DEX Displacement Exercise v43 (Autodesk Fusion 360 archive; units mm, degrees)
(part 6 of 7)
sketch "Sketch35" plane through (0, 0, 0) normal (0, 0, 1) x axis (1, 0, 0)
  line L1 (8, 6) -> (-6, 6)
  line L2 (8, -10) -> (8, 6)
  line L3 (-6, -10) -> (8, -10)
  line L4 (-6, 6) -> (-6, -10)
  line L5 (5.46, 30) -> (5.46, 6)
  line L6 (8, 21) -> (8, 6)
  line L7 (10, 21) -> (8, 21)
  line L8 (10, -10) -> (10, 21)
  line L9 (20, -10) -> (10, -10)
  line L10 (20, 30) -> (20, -10)
  line L11 (5.46, 30) -> (20, 30)
  line L12 (5.46, 21) -> (8, 21)
  circle C1 centre (0, 0) radius 8
  circle C2 centre (0, 0) radius 3
  circle C3 centre (0, 0) radius 4.5
  circle C4 centre (6, -6) radius 2.5
  circle C5 centre (15, 0) radius 2.7
  circle C6 centre (15, 25) radius 2.7
  circle C7 centre (15, 25) radius 1.625
  circle C8 centre (15, 0) radius 1.625
  circle C9 centre (15, 15) radius 2.7
  circle C10 centre (15, 15) radius 1.625
  circle C11 centre (15, -6) radius 2
  circle C12 centre (15, -6) radius 1.9
  circle C13 centre (15, 15) radius 3.625
  circle C14 centre (15, 25) radius 3.625
  circle C15 centre (15, 0) radius 3.625
  point P9 (4.5, 0)
  point P2 (0, 0)
  point P4 (0, 0)
  point P3 (0, 0)
  point P1 (0, 0)
  point P11 (5.46, 6)
  point P12 (5.46, 30)
  point P18 (5.46, 30)
  point P7 (8, -10)
  point P19 (15, 0)
  point P20 (15, 25)
  point P23 (5.46, 21)
  point P26 (15, -6)
  point P21 (15, 25)
  point P25 (15, 15)
  point P29 (11.375, 15)
  point P10 (6, -6)
  point P13 (8, 21)
  point P14 (10, 21)
  point P6 (8, 6)
  point P15 (10, -10)
  point P16 (20, -10)
  point P24 (15, 15)
  horizontal L1
  vertical L2
  horizontal L3
  vertical L4
  coincident C3 P9
  horizontal P2 P9
  coincident P2 P4
  coincident P2 P3
  coincident P1 P4
  coincident L1 P11
  perpendicular L1 L5
  perpendicular L1 L6
  perpendicular L6 L7
  perpendicular L7 L8
  perpendicular L8 L9
  perpendicular L9 L10
  perpendicular L10 L11
  coincident P12 P18
  coincident P7 L9
  horizontal P1 P19
  equal C5 C6
  vertical P19 P20
  concentric C6 C7
  concentric C5 C8
  equal C7 C8
  coincident L5 P23
  perpendicular L5 L12
  equal C6 C9
  concentric C9 C10
  vertical P19 P26
  concentric C11 C12
  vertical P21 P25
  concentric C10 C13
  coincident C13 P29
  horizontal P25 P29
  concentric C7 C14
  concentric C5 C15
  equal C14 C15
  equal C13 C14
  dimension "d1328" diameter C1 = 16 (= "od_bearings")
  dimension "d1329" diameter C2 = 6 (= "hw_m4insert_d")
  dimension "d1330" diameter C3 = 9
  dimension "d1361" distance P2 L1 = 6
  dimension "d1362" distance P2 L3 = 10
  dimension "d1363" distance P4 L4 = 6 (= "d1361")
  dimension "d1458" diameter C4 = 5
  dimension "d1459" distance L2 P10 = 2
  dimension "d1460" distance P2 P10 = 6
  dimension "d1461" distance L5 L6 = 2.54
  dimension "d1462" distance P13 P14 = 2
  dimension "d1463" distance P6 P13 = 15
  dimension "d1464" distance P4 P7 = 8
  dimension "d1465" distance P15 P16 = 10
  dimension "d1467" distance P13 L11 = 9
  dimension "d1468" distance L11 P20 = 5
  dimension "d1469" diameter C6 = 5.4 (= "hw_m3insert_d")
  dimension "d1470" distance L10 P19 = 5 (= "d1465 / 2")
  dimension "d1471" diameter C7 = 3.25
  dimension "d1502" = 26
  dimension "d1503" = 41
  dimension "d1506" distance P20 P24 = 10
  dimension "d1507" diameter C10 = 3.25
  dimension "d1508" distance L9 P26 = 4
  dimension "d1509" diameter C11 = 4
  dimension "d1510" distance C11 C12 = 0.1
  dimension "d1528" diameter C13 = 7.25
  dimension "d1529" = 1.25
  dimension "d1447" leftDistance = 0.5
  dimension "d1449" distance = 5
  dimension "d1450" distance = 15
  dimension "d1452" distance = 5
  dimension "d1453" distance = 4.9
  dimension "d1454" distance = 4.9
  dimension "d1455" distance = 5
  dimension "d1456" distance = 24.9
  dimension "d531" countU = 13 (= "nh_gantry_length + 1")
  dimension "d532" CountV = 9 (= "nh_gantry_width + 1")
  dimension "d533" uSpaceDistance = 10
  dimension "d534" vSpaceDistance = -10
  dimension "d535" diameter = 3.3 (= "hw_m4_tappedwj")
  dimension "d541" uSpaceDistance = 10
  dimension "d542" vSpaceDistance = 10
  dimension "d560" distance = 6.6 (= "t_sheet_MAIN")
  dimension "d563" distance = 5 (= "t_bearings")
  dimension "d564" distance = 16 (= "od_bearings")
  dimension "d565" angle = 45 (= "d566")
  dimension "d566" angle = 45
  dimension "d567" distance = 10 (= "l_shoulder_thread")
  dimension "d568" distance = 6.6 (= "t_sheet_MAIN")
  dimension "d569" distance = 45 (= "( ( nh_gantry_width * 10 ) * 1 mm + 10 mm ) / 2")
  dimension "d571" distance = 4.5 (= "hw_shoulder_headHeight + 0.5 mm")
  dimension "d572" distance = 4.5 (= "hw_shoulder_headDiameter / 2")
  dimension "d574" distance = 8.8037
  dimension "d576" distance = 0.5
  dimension "d577" distance = 0.5
  dimension "d580" distance = 0.5
  dimension "d581" distance = 3.5 (= "hw_m4insert_d / 2 + 0.5 mm")
  dimension "d582" distance = 3.5 (= "d581")
  dimension "d583" distance = 2.1
  dimension "d584" distance = 0.8383
  dimension "d586" distance = 1.269 (= "0.5 mm + 0.769 mm")
  dimension "d587" distance = 5
  dimension "d588" distance = 10
  dimension "d589" distance = 5
  dimension "d590" AlongDistance = 65 (= "( nh_gantry_length * 10 + 10 ) / 2 * 1 mm")
  dimension "d591" TaperAngle = 0
  dimension "d597" ProfileOffset = 0.25 (= "carriage_offsets")
  dimension "d599" TaperAngle = 0
  dimension "d601" diameter = 16 (= "od_bearings")
  dimension "d602" diameter = 6 (= "hw_m4insert_d")
  dimension "d603" diameter = 4
  dimension "d604" distance = 0.25
  dimension "d606" AlongDistance = -20
  dimension "d607" TaperAngle = 0
  dimension "d608" ProfileOffset = 0.5
  dimension "d609" AlongDistance = 5 (= "t_bearings")
  dimension "d610" TaperAngle = 0
  dimension "d612" distance = 0.25
  dimension "d613" diameter = 4
  dimension "d614" diameter = 6 (= "hw_m4insert_d")
  dimension "d615" diameter = 16 (= "od_bearings")
  dimension "d616" AlongDistance = -20
  dimension "d617" TaperAngle = 0
  dimension "d618" ProfileOffset = 0.5
  dimension "d619" AlongDistance = 5 (= "t_bearings")
  dimension "d620" TaperAngle = 0
  dimension "d621" AlongDistance = 670 (= "l_actual_complete")
  dimension "d622" TaperAngle = 0
  dimension "d623" distance = 0.1
  dimension "d624" distance = 1.6455
  dimension "d625" distance = 3.4128
  dimension "d626" distance = 13.2 (= "0.5 in + 0.5 mm")
  dimension "d628" distance = 5
  dimension "d630" distance = 30
  dimension "d631" diameter = 4.064 (= "hw_n6_thru")
  dimension "d636" diameter = 6.6548 (= "hw_n6_flathead")
  dimension "d637" diameter = 3.1 (= "hw_n6_thread")
  dimension "d638" distance = 4
  dimension "d639" distance = 4 (= "d638")
  dimension "d641" TaperAngle = 0
  dimension "d642" ProfileOffset = 0
  dimension "d643" Side1Offset = 0
  dimension "d644" TaperAngle = 0
  dimension "d645" ProfileOffset = 0
  dimension "d646" Side1Offset = 0
  dimension "d647" TaperAngle = 0
  dimension "d648" distance = 5
  dimension "d649" distance = 0.75
  dimension "d650" ProfileOffset = 0
  dimension "d651" Side1Offset = 0
  dimension "d652" TaperAngle = 0
  dimension "d653" AlongDistance = 21
  dimension "d654" TaperAngle = 0
  dimension "d655" distance = 1
  dimension "d656" ProfileOffset = 0
  dimension "d657" Side1Offset = 0
  dimension "d658" TaperAngle = 0
  dimension "d659" AlongDistance = 12
  dimension "d660" TaperAngle = 0
  dimension "d661" Side1Offset = 0
  dimension "d662" TaperAngle = 0
  dimension "d667" Radius = 4
  dimension "d669" Radius = 4
  dimension "d670" Radius = 1
  dimension "d673" Radius = 0.5
  dimension "d674" Radius = 0.5
  dimension "d675" Radius = 0.5
  dimension "d676" Radius = 0.5
  dimension "d677" Radius = 0.2
  dimension "d680" distance = 40
  dimension "d681" distance = 6
  dimension "d691" distance = 2.54
  dimension "d692" distance = 0.5 (= "d689")
  dimension "d693" distance = 0.5
  dimension "d696" distance = 0.5
  dimension "d697" distance = 5
  dimension "d701" distance = 1.7
  dimension "d702" distance = 1.7 (= "d701")
  dimension "d706" distance = 2.54 (= "d691")
  dimension "d707" distance = 3.5
  dimension "d708" distance = 0.5
  dimension "d709" ProfileOffset = 0
  dimension "d710" Side1Offset = 0
  dimension "d711" TaperAngle = 0
  dimension "d712" ProfileOffset = 0
  dimension "d713" Side1Offset = 5
  dimension "d714" TaperAngle = 0
  dimension "d715" Side1Offset = 0
  dimension "d716" TaperAngle = 0
  dimension "d717" distance = 0.75
  dimension "d718" distance = 1.7
  dimension "d719" diameter = 16 (= "od_bearings")
  dimension "d720" diameter = 6 (= "hw_m4insert_d")
  dimension "d721" diameter = 4
  dimension "d722" distance = 0.25
  dimension "d723" AlongDistance = -19
  dimension "d724" TaperAngle = 0
  dimension "d725" distance = 1
  dimension "d726" ProfileOffset = 0.5
  dimension "d727" AlongDistance = 5 (= "t_bearings")
  dimension "d728" TaperAngle = 0
  dimension "d729" diameter = 4
  dimension "d730" diameter = 6 (= "hw_m4insert_d")
  dimension "d731" diameter = 16 (= "od_bearings")
  dimension "d732" distance = 1
  dimension "d733" distance = 0.25
  dimension "d734" AlongDistance = -26
  dimension "d735" TaperAngle = 0
  dimension "d736" ProfileOffset = 0.5
  dimension "d737" AlongDistance = 5 (= "t_bearings")
  dimension "d738" TaperAngle = 0
  dimension "d739" distance = 6
  dimension "d740" ProfileOffset = 0
  dimension "d741" Side1Offset = 0
  dimension "d742" TaperAngle = 0
  dimension "d743" Radius = 4
  dimension "d744" distance = -1
  dimension "d745" AlongDistance = 32
  dimension "d746" TaperAngle = 0
  dimension "d747" distance = 0.5
  dimension "d748" distance = 1
  dimension "d749" ProfileOffset = 0
  dimension "d750" AlongDistance = 3
  dimension "d751" TaperAngle = 0
  dimension "d752" ProfileOffset = 0
  dimension "d753" Side1Offset = 0
  dimension "d754" TaperAngle = 0
  dimension "d755" Side1Offset = 0
  dimension "d756" TaperAngle = 0
  dimension "d757" ProfileOffset = 0
  dimension "d758" Side1Offset = 0
  dimension "d759" TaperAngle = 0
  dimension "d760" AlongDistance = 12
  dimension "d761" TaperAngle = 0
  dimension "d762" AlongDistance = -37
  dimension "d763" TaperAngle = 0
  dimension "d764" Side1Offset = 0.5
  dimension "d765" TaperAngle = 0
  dimension "d767" Radius = 3
  dimension "d768" Radius = 2
  dimension "d770" Radius = 3
  dimension "d771" Radius = 3
  dimension "d772" distance = 3
  dimension "d773" distance = 3
  dimension "d774" Radius = 1
  dimension "d775" Radius = 0.5
  dimension "d776" Radius = 2
  dimension "d777" diameter = 5.4 (= "hw_m3insert_d")
  dimension "d778" diameter = 3.5 (= "hw_m3_thru")
  dimension "d779" Side1Offset = 0
  dimension "d780" TaperAngle = 0
  dimension "d781" Side1Offset = 0
  dimension "d782" TaperAngle = 0
  dimension "d783" Radius = 2
  dimension "d784" Radius = 2
  dimension "d785" Radius = 2
  dimension "d786" Radius = 3
  dimension "d788" Radius = 0.5
  dimension "d789" distance = 12
  dimension "d790" distance = 2
  dimension "d791" angle = 45
  dimension "d793" Radius = 2
  dimension "d794" Radius = 2
  dimension "d795" Radius = 1
  dimension "d797" Radius = 2
  dimension "d798" Radius = 1
  dimension "d799" Radius = 2
  dimension "d800" Radius = 4.5
  dimension "d801" distance = 0.275 (= "preload_bearings / 2")
  dimension "d803" distance = -0.5
  dimension "d806" distance = 3
  dimension "d807" AlongDistance = -60
  dimension "d808" distance = 3.8274 (= "d430 / 2")
  dimension "d809" distance = 0.423 (= "1 mm - 0.577 mm")
  dimension "d810" distance = 0.5
  dimension "d813" Side1Offset = 0
  dimension "d814" TaperAngle = 0
  dimension "d815" distance = 0.1
  dimension "d816" distance = 1.75
  dimension "d818" distance = 35
  dimension "d820" distance = 5
  dimension "d821" distance = 5
  dimension "d822" diameter = 4.064 (= "hw_n6_thru")
  dimension "d823" diameter = 6.6548 (= "hw_n6_flathead")
  dimension "d824" distance = 0.6
  dimension "d825" distance = 0.6 (= "d824")
  dimension "d827" TaperAngle = 0
  dimension "d828" diameter = 3.1 (= "hw_n6_thread")
  dimension "d829" Side1Offset = 0
  dimension "d830" TaperAngle = 0
  dimension "d831" distance = 4
  dimension "d832" distance = 4.477 (= "d833")
  dimension "d833" distance = 4.477 (= "d477")
  dimension "d836" diameter = 6.6548 (= "hw_n6_flathead")
  dimension "d839" Side1Offset = 0
  dimension "d840" TaperAngle = 0
  dimension "d841" distance = 0.9
  dimension "d842" angle = 50
  dimension "d843" angle = 50
  dimension "d844" distance = 8
  dimension "d845" distance = 5
  dimension "d846" diameter = 4.5
  dimension "d847" AlongDistance = -7
  dimension "d848" TaperAngle = 0
  dimension "d849" leftDistance = 0.75
  dimension "d850" ProfileOffset = 0
  dimension "d851" Side1Offset = 0
  dimension "d852" TaperAngle = 0
  dimension "d853" ProfileOffset = 0
  dimension "d854" Side1Offset = 0
  dimension "d855" TaperAngle = 0
  dimension "d856" distance = 12.7
  dimension "d857" leftDistance = 1.5
  dimension "d858" distance = 1.5454
  dimension "d859" Radius = 4
  dimension "d860" Radius = 2
  dimension "d861" Radius = 2
  dimension "d862" Radius = 4
  dimension "d863" Radius = 2
  dimension "d864" Radius = 35
  dimension "d865" Radius = 4
  dimension "d866" Radius = 1
  dimension "d869" Side1Offset = 0
  dimension "d870" TaperAngle = 0
  dimension "d872" distance = 1.5
  dimension "d873" leftDistance = 1.5
  dimension "d874" Radius = 2
  dimension "d885" distance = 27.775
  dimension "d886" distance = 30.275 (= "30 mm + preload_bearings / 2")
  dimension "d889" diameter = 3.3 (= "hw_m4_tappedwj")
  dimension "d890" distance = 5
  dimension "d891" distance = 10.275 (= "10 mm + preload_bearings / 2")
  dimension "d893" TaperAngle = 0
  dimension "d894" distance = 17.5
  dimension "d895" distance = 27.5
  dimension "d896" distance = 0.2
  dimension "d897" distance = 0.2 (= "d896")
  dimension "d900" distance = 6
  dimension "d902" distance = 3.7 (= "2 mm + 1.2 mm + 0.5 mm")
  dimension "d903" distance = 1
  dimension "d904" distance = 8
  dimension "d905" distance = 2.54
  dimension "d906" distance = 2.54
  dimension "d907" distance = 2.54
  dimension "d908" Side1Offset = 0
  dimension "d909" TaperAngle = 0
  dimension "d910" ProfileOffset = 0
  dimension "d911" Side1Offset = 0
  dimension "d912" TaperAngle = 0
  dimension "d913" leftDistance = 1.5
  dimension "d915" distance = 5.65
  dimension "d916" distance = 14.65
  dimension "d917" distance = 14.65
  dimension "d918" Side1Offset = 0
  dimension "d919" TaperAngle = 0
  dimension "d920" ChordLen = 4
  dimension "d921" ChordLen = 1
  dimension "d923" distance = 2.54
  dimension "d924" Radius = 2
extrude "Extrude157" new body sketch "Sketch35" profile of C1 C2 C3 L1 L2 L3 L4 C4 L5 L6 L7 L8 L9 L10 L11 C7 C8 L12 blind -8 from offset -5.75 (= "( -11.5 / 2 ) * 1 mm")
extrude "Extrude162" sketch "Sketch35" profile of C1 L2 C4 blind -8
fillet "Fillet111" radius 0.4
sketch "Sketch38" plane through (20, 0, 0) normal (1, 0, 0) x axis (0, 1, 0)
  line L1 (-10, -5.75) -> (30, -5.75)
  line L2 (-10, -13.75) -> (-10, -5.75)
  line L3 (30, -13.75) -> (-10, -13.75)
  line L4 (30, -5.75) -> (30, -13.75)
  line L5 (-10, -9.75) -> (-6, -9.75)
  circle C1 centre (-6, -9.75) radius 1.575
  circle C2 centre (-6, -9.75) radius 2.7
  point P6 (-6, -9.75)
  point P8 (-6, -9.75)
  point P9 (-10, -9.75)
  concentric C1 C2
  coincident P6 P8
  horizontal L5
  midpoint L2 P9
  dimension "d1539" diameter C2 = 5.4 (= "hw_m3insert_d")
  dimension "d1540" distance L2 P6 = 4
  dimension "d1541" diameter C1 = 3.15
extrude "Extrude170" cut sketch "Sketch38" profile of C1 to an object
extrude "Extrude171" cut sketch "Sketch38" profile of C1 C2 against normal blind 6
chamfer "Chamfer46" distance 1
chamfer "Chamfer47" distance 0.3
mirror "Mirror12"
extrude "Extrude158" add sketch "Sketch35" profile of L5 L7 L8 L9 L10 L11 C7 C8 L12 to an object from offset 0.1
extrude "Extrude160" add sketch "Sketch35" profile of L5 L7 L8 L9 L10 L11 C7 C8 L12 to an object from offset -0.1
extrude "Extrude159" sketch "Sketch35" profile of C2 C3 blind 4.5
chamfer "Chamfer37" distance 0.5
chamfer "Chamfer38" distance 0.5
chamfer "Chamfer39" distance 0.5
extrude "Extrude161" add sketch "Sketch35" profile of C1 C2 C3 L1 L4 C4 blind 5 from offset 0.5
mirror "Mirror13"
fillet "Fillet108" radius 6
fillet "Fillet109" radius 1
fillet "Fillet110" radius 2
fillet "Fillet112" radius 0.5
extrude "Extrude163" cut sketch "Sketch35" profile of C10 to an object
extrude "Extrude164" sketch "Sketch35" profile of C9 C10 blind 6
extrude "Extrude165" cut sketch "Sketch35" profile of C11 C12 against normal blind 4
chamfer "Chamfer40" distance 1
chamfer "Chamfer41" distance 0.5
extrude "Extrude166" add sketch "Sketch35" profile of C12 along normal blind 2 and against normal blind 2
chamfer "Chamfer42" distance 1
chamfer "Chamfer43" distance 1
extrude "Extrude167" cut sketch "Sketch35" profile of C7 C8 C10 to an object
extrude "Extrude168" cut sketch "Sketch35" profile of C7 C8 C9 C10 C13 C14 C15 to an object from offset 3
chamfer "Chamfer44" distance 2
chamfer "Chamfer45" distance 0.5
extrude "Extrude169" cut sketch "Sketch35" profile of C7 C8 to an object
fillet "Fillet113" radius 2
fillet "Fillet114" radius 0.5
sketch "Sketch39" plane through (0, 0, -13.75) normal (0, 0, -1) x axis (1, 0, 0)
  line L1 (10, -20) -> (10, 9.5)
  line L2 (8, 3.5813) -> (8, -20)
  line L3 (8, 9.5) -> (8, 8.4187)
  line L4 (-4, 10) -> (7.5, 10)
  line L5 (-6, 0) -> (-6, 8)
  line L6 (4.46, -6) -> (0, -6)
  line L7 (5.46, -28) -> (5.46, -7)
  line L8 (18, -30) -> (7.46, -30)
  line L9 (20, 8) -> (20, -28)
  line L10 (10.5, 10) -> (18, 10)
  line L11 (-22.6301, -2.7786) -> (0, 0)
  line L12 (-22.8, 0) -> (0, 0)
  circle C1 centre (15, -25) radius 1.625
  circle C2 centre (15, 0) radius 1.625
  circle C3 centre (0, 0) radius 3
  circle C4 centre (15, -15) radius 3.2
  arc A1 centre (10.5, 9.5) radius 0.5 clockwise from (10, 9.5) to (10.5, 10)
  arc A2 centre (9, -20) radius 1 clockwise from (10, -20) to (8, -20)
  arc A3 centre (7.6, 3.5813) radius 0.4 clockwise from (7.3793, 3.9149) to (8, 3.5813)
  arc A4 centre (6, 6) radius 2.5 clockwise from (7.3793, 3.9149) to (7.3793, 8.0851)
  arc A5 centre (7.6, 8.4187) radius 0.4 clockwise from (8, 8.4187) to (7.3793, 8.0851)
  arc A6 centre (7.5, 9.5) radius 0.5 clockwise from (7.5, 10) to (8, 9.5)
  arc A7 centre (-4, 8) radius 2 clockwise from (-6, 8) to (-4, 10)
  arc A8 centre (0, 0) radius 6 clockwise from (0, -6) to (-6, 0)
  arc A9 centre (4.46, -7) radius 1 clockwise from (4.46, -6) to (5.46, -7)
  arc A10 centre (7.46, -28) radius 2 clockwise from (7.46, -30) to (5.46, -28)
  arc A11 centre (18, -28) radius 2 clockwise from (20, -28) to (18, -30)
  arc A12 centre (18, 8) radius 2 clockwise from (18, 10) to (20, 8)
  circle C5 centre (-22.6301, -2.7786) radius 19.1
  arc A13 centre (0, 0) radius 22.8 clockwise from (-22.6301, -2.7786) to (-22.8, 0)
  point P4 (0, 0)
  point P40 (0, 0)
  point P39 (-22.6301, -2.7786)
  point P41 (-22.6301, -2.7786)
  point P43 (-3.6724, -0.4509)
  point P44 (-2.9776, -0.3656)
  point P47 (-22.6301, -2.7786)
  point P45 (0, 0)
  point P42 (-22.8, 0)
  point P46 (-22.8, 0)
  coincident P4 P40
  coincident P39 P41
  perpendicular L5 L12
  coincident C5 P43
  coincident L11 P43
  coincident L11 P44
  coincident C3 P44
  coincident P39 P47
  coincident P40 P45
  coincident P42 P46
  dimension "d1548" diameter C5 = 38.2
  dimension "d1549" angle L11 L12 = 7
  dimension "d1550" distance P43 P44 = 0.7
extrude "Extrude172" cut sketch "Sketch39" profile of L5 A8 C5 against normal blind 5
chamfer "Chamfer48" distance 2.2

design "dex-fixtures-typefive"
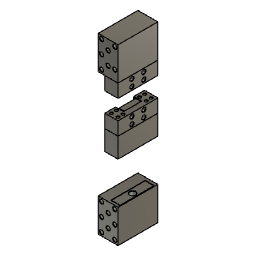
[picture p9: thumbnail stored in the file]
parameter "t_sheet_MAIN" = 6.7 comment "thickness of *most* of the gantry material"
parameter "t_sheet_SECOND" = 6.35 (= "1 / 4 * 1") comment "thickness of the webs"
parameter "od_bearings" = 16
parameter "id_bearings" = 5
parameter "t_bearings" = 5
parameter "p_belt" = 2
parameter "w_belt" = 10
parameter "t_belt" = 1.4
parameter "l_top_belt_to_rail" = 3
parameter "r_cutoutTool" = 2.05 (= "4.1 mm / 2")
parameter "hw_m3_thru" = 3.5
parameter "hw_m3_head" = 5.5
parameter "hw_m3_washer" = 7
parameter "hw_m3_thread" = 2.5
parameter "tab_breather" = 0.2 comment "tab clearance"
parameter "hw_m5_thread" = 4.2
parameter "hw_m5_head" = 8.5
parameter "hw_m5_washer" = 10
parameter "hw_m5_thru" = 5.25
parameter "hw_m6_thru" = 6.5
parameter "hw_m6_head" = 10
parameter "hw_m6_washer" = 12
parameter "l_beltblock" = 15
parameter "hw_plstf6_thread" = 2.94
parameter "hw_plstf6_thru" = 4
parameter "hw_plstf6_head" = 6.86
parameter "hw_plstf6_washer" = 7.92
parameter "hw_m3_flathead" = 6
parameter "hw_m4insert_d" = 6
parameter "hw_m4insert_l" = 4.8
parameter "hw_m4_tappedwj" = 3.3
parameter "hw_m4_thru" = 4.25
parameter "hw_m4_head" = 7
parameter "hw_m4_headheight" = 4
parameter "preload_bearings" = 0.55
parameter "hw_m3insert_d" = 5.4
parameter "hw_m3insert_l" = 3.8
parameter "dist_clearance" = 0.5
parameter "hw_shoulder_headDiameter" = 9
parameter "hw_shoulder_headHeight" = 4
parameter "l_travel" = 405 comment "will be rounded to 10s"
parameter "User Parameter" = 0 (= "min 10")
parameter "nh_rail_width" = "nh_gantry_width - 3"
parameter "l_shoulder_thread" = 10
parameter "hw_n6_thru" = 4.064
parameter "hw_n6_thread" = 3.1
parameter "hw_n6_flathead" = 6.6548
parameter "hw_n6_head" = 6.858
parameter "carriage_offsets" = 0.25
parameter "hw_momentPin_reald" = 3.683
parameter "pinch_by" = 0.2
parameter "d285" = 2
parameter "d344" = 3.5
parameter "d482" = 3.35 (= "t_sheet_MAIN / 2")
parameter "d578" = 0.5
parameter "d683" = 3.683 (= "hw_momentPin_reald")
parameter "d689" = 0.5
parameter "d698" = 5
parameter "d705" = 3.5415 (= "d683 / 2 + 1.7 mm")
parameter "d837" = 0.25
sketch "Sketch41" plane through (0, 0, 0) normal (0, 0, 1) x axis (1, 0, 0)
  line L1 (6.5, 25.5) -> (-6.5, 25.5)
  line L2 (6.5, -25.5) -> (6.5, 25.5)
  line L3 (-6.5, -25.5) -> (6.5, -25.5)
  line L4 (-6.5, 25.5) -> (-6.5, -25.5)
  line L5 (-6.5, -25.5) -> (6.5, 25.5)
  line L6 (-22, 30) -> (8, 30)
  line L7 (-22, -30) -> (-22, 30)
  line L8 (8, -30) -> (-22, -30)
  line L9 (8, 30) -> (8, -30)
  line L10 (-22, 0) -> (8, 0)
  circle C1 centre (0, 0) radius 4
  circle C2 centre (0, 0) radius 8.25
  circle C3 centre (0, 0) radius 4.25
  circle C4 centre (0, 0) radius 6.75
  point P6 (0, 0)
  point P1 (0, 0)
  point P11 (8, 0)
  point P14 (0, 0)
  point P15 (8, 0)
  point P16 (-22, 0)
  point P3 (6.5, 25.5)
  point P4 (6.5, -25.5)
  point P2 (-6.5, 25.5)
  point P7 (8, 30)
  point P10 (8, -30)
  point P8 (-22, 30)
  horizontal L1
  vertical L2
  horizontal L3
  vertical L4
  midpoint L5 P6
  coincident P1 P6
  horizontal L6
  vertical L7
  horizontal L8
  vertical L9
  midpoint L9 P11
  horizontal P6 P11
  concentric C1 C2
  concentric C1 C3
  coincident P1 P14
  coincident P11 P15
  midpoint L7 P16
  dimension "d1569" distance P3 P4 = 51
  dimension "d1570" distance P2 P3 = 13
  dimension "d1571" diameter C1 = 8
  dimension "d1572" distance P7 P10 = 60
  dimension "d1573" distance P7 P8 = 30
  dimension "d1575" distance P1 L9 = 8
  dimension "d1576" diameter C2 = 16.5
  dimension "d1577" diameter C3 = 8.5
  dimension "d1578" diameter C4 = 13.5
  dimension "d560" distance = 6.6 (= "t_sheet_MAIN")
  dimension "d563" distance = 5 (= "t_bearings")
  dimension "d564" distance = 16 (= "od_bearings")
  dimension "d565" angle = 45 (= "d566")
  dimension "d566" angle = 45
  dimension "d567" distance = 10 (= "l_shoulder_thread")
  dimension "d568" distance = 6.6 (= "t_sheet_MAIN")
  dimension "d569" distance = 45 (= "( ( nh_gantry_width * 10 ) * 1 mm + 10 mm ) / 2")
  dimension "d571" distance = 4.5 (= "hw_shoulder_headHeight + 0.5 mm")
  dimension "d572" distance = 4.5 (= "hw_shoulder_headDiameter / 2")
  dimension "d574" distance = 8.8037
  dimension "d576" distance = 0.5
  dimension "d577" distance = 0.5
  dimension "d580" distance = 0.5
  dimension "d581" distance = 3.5 (= "hw_m4insert_d / 2 + 0.5 mm")
  dimension "d582" distance = 3.5 (= "d581")
  dimension "d583" distance = 2.1
  dimension "d584" distance = 0.8383
  dimension "d586" distance = 1.269 (= "0.5 mm + 0.769 mm")
  dimension "d587" distance = 5
  dimension "d588" distance = 10
  dimension "d589" distance = 5
  dimension "d590" AlongDistance = 65 (= "( nh_gantry_length * 10 + 10 ) / 2 * 1 mm")
  dimension "d591" TaperAngle = 0
  dimension "d597" ProfileOffset = 0.25 (= "carriage_offsets")
  dimension "d599" TaperAngle = 0
  dimension "d601" diameter = 16 (= "od_bearings")
  dimension "d602" diameter = 6 (= "hw_m4insert_d")
  dimension "d603" diameter = 4
  dimension "d604" distance = 0.25
  dimension "d606" AlongDistance = -20
  dimension "d607" TaperAngle = 0
  dimension "d608" ProfileOffset = 0.5
  dimension "d609" AlongDistance = 5 (= "t_bearings")
  dimension "d610" TaperAngle = 0
  dimension "d612" distance = 0.25
  dimension "d613" diameter = 4
  dimension "d614" diameter = 6 (= "hw_m4insert_d")
  dimension "d615" diameter = 16 (= "od_bearings")
  dimension "d616" AlongDistance = -20
  dimension "d617" TaperAngle = 0
  dimension "d618" ProfileOffset = 0.5
  dimension "d619" AlongDistance = 5 (= "t_bearings")
  dimension "d620" TaperAngle = 0
  dimension "d621" AlongDistance = 670 (= "l_actual_complete")
  dimension "d622" TaperAngle = 0
  dimension "d623" distance = 0.1
  dimension "d624" distance = 1.6455
  dimension "d625" distance = 3.4128
  dimension "d626" distance = 13.2 (= "0.5 in + 0.5 mm")
  dimension "d628" distance = 5
  dimension "d630" distance = 30
  dimension "d631" diameter = 4.064 (= "hw_n6_thru")
  dimension "d636" diameter = 6.6548 (= "hw_n6_flathead")
  dimension "d637" diameter = 3.1 (= "hw_n6_thread")
  dimension "d638" distance = 4
  dimension "d639" distance = 4 (= "d638")
  dimension "d641" TaperAngle = 0
  dimension "d642" ProfileOffset = 0
  dimension "d643" Side1Offset = 0
  dimension "d644" TaperAngle = 0
  dimension "d645" ProfileOffset = 0
  dimension "d646" Side1Offset = 0
  dimension "d647" TaperAngle = 0
  dimension "d648" distance = 5
  dimension "d649" distance = 0.75
  dimension "d650" ProfileOffset = 0
  dimension "d651" Side1Offset = 0
  dimension "d652" TaperAngle = 0
  dimension "d653" AlongDistance = 21
  dimension "d654" TaperAngle = 0
  dimension "d655" distance = 1
  dimension "d656" ProfileOffset = 0
  dimension "d657" Side1Offset = 0
  dimension "d658" TaperAngle = 0
  dimension "d659" AlongDistance = 12
  dimension "d660" TaperAngle = 0
  dimension "d661" Side1Offset = 0
  dimension "d662" TaperAngle = 0
  dimension "d667" Radius = 4
  dimension "d669" Radius = 4
  dimension "d670" Radius = 1
  dimension "d673" Radius = 0.5
  dimension "d674" Radius = 0.5
  dimension "d675" Radius = 0.5
  dimension "d676" Radius = 0.5
  dimension "d677" Radius = 0.2
  dimension "d680" distance = 40
  dimension "d681" distance = 6
  dimension "d691" distance = 2.54
  dimension "d692" distance = 0.5 (= "d689")
  dimension "d693" distance = 0.5
  dimension "d696" distance = 0.5
  dimension "d697" distance = 5
  dimension "d701" distance = 1.7
  dimension "d702" distance = 1.7 (= "d701")
  dimension "d706" distance = 2.54 (= "d691")
  dimension "d707" distance = 3.5
  dimension "d708" distance = 0.5
  dimension "d709" ProfileOffset = 0
  dimension "d710" Side1Offset = 0
  dimension "d711" TaperAngle = 0
  dimension "d712" ProfileOffset = 0
  dimension "d713" Side1Offset = 5
  dimension "d714" TaperAngle = 0
  dimension "d715" Side1Offset = 0
  dimension "d716" TaperAngle = 0
  dimension "d717" distance = 0.75
  dimension "d718" distance = 1.7
  dimension "d719" diameter = 16 (= "od_bearings")
  dimension "d720" diameter = 6 (= "hw_m4insert_d")
  dimension "d721" diameter = 4
  dimension "d722" distance = 0.25
  dimension "d723" AlongDistance = -19
  dimension "d724" TaperAngle = 0
  dimension "d725" distance = 1
  dimension "d726" ProfileOffset = 0.5
  dimension "d727" AlongDistance = 5 (= "t_bearings")
  dimension "d728" TaperAngle = 0
  dimension "d729" diameter = 4
  dimension "d730" diameter = 6 (= "hw_m4insert_d")
  dimension "d731" diameter = 16 (= "od_bearings")
  dimension "d732" distance = 1
  dimension "d733" distance = 0.25
  dimension "d739" distance = 6
  dimension "d743" Radius = 4
  dimension "d744" distance = -1
  dimension "d747" distance = 0.5
  dimension "d748" distance = 1
  dimension "d767" Radius = 3
  dimension "d768" Radius = 2
  dimension "d770" Radius = 3
  dimension "d771" Radius = 3
  dimension "d772" distance = 3
  dimension "d773" distance = 3
  dimension "d774" Radius = 1
  dimension "d775" Radius = 0.5
  dimension "d776" Radius = 2
  dimension "d777" diameter = 5.4 (= "hw_m3insert_d")
  dimension "d778" diameter = 3.5 (= "hw_m3_thru")
  dimension "d783" Radius = 2
  dimension "d784" Radius = 2
  dimension "d785" Radius = 2
  dimension "d786" Radius = 3
  dimension "d788" Radius = 0.5
  dimension "d789" distance = 12
  dimension "d790" distance = 2
  dimension "d791" angle = 45
  dimension "d793" Radius = 2
  dimension "d794" Radius = 2
  dimension "d795" Radius = 1
  dimension "d797" Radius = 2
  dimension "d798" Radius = 1
  dimension "d799" Radius = 2
  dimension "d800" Radius = 4.5
  dimension "d801" distance = 0.275 (= "preload_bearings / 2")
  dimension "d803" distance = -0.5
  dimension "d806" distance = 3
  dimension "d807" AlongDistance = -60
  dimension "d808" distance = 3.8274 (= "d430 / 2")
  dimension "d809" distance = 0.423 (= "1 mm - 0.577 mm")
  dimension "d810" distance = 0.5
  dimension "d815" distance = 0.1
  dimension "d816" distance = 1.75
  dimension "d818" distance = 35
  dimension "d820" distance = 5
  dimension "d821" distance = 5
  dimension "d822" diameter = 4.064 (= "hw_n6_thru")
  dimension "d823" diameter = 6.6548 (= "hw_n6_flathead")
  dimension "d824" distance = 0.6
  dimension "d825" distance = 0.6 (= "d824")
  dimension "d828" diameter = 3.1 (= "hw_n6_thread")
  dimension "d831" distance = 4
  dimension "d832" distance = 4.477 (= "d833")
  dimension "d833" distance = 4.477 (= "d477")
  dimension "d836" diameter = 6.6548 (= "hw_n6_flathead")
  dimension "d841" distance = 0.9
  dimension "d842" angle = 50
  dimension "d843" angle = 50
  dimension "d844" distance = 8
  dimension "d845" distance = 5
  dimension "d846" diameter = 4.5
  dimension "d849" leftDistance = 0.75
  dimension "d856" distance = 12.7
  dimension "d857" leftDistance = 1.5
  dimension "d858" distance = 1.5454
  dimension "d859" Radius = 4
  dimension "d860" Radius = 2
  dimension "d861" Radius = 2
  dimension "d862" Radius = 4
  dimension "d863" Radius = 2
  dimension "d864" Radius = 35
  dimension "d865" Radius = 4
  dimension "d866" Radius = 1
  dimension "d872" distance = 1.5
  dimension "d873" leftDistance = 1.5
  dimension "d874" Radius = 2
  dimension "d885" distance = 27.775
  dimension "d886" distance = 30.275 (= "30 mm + preload_bearings / 2")
  dimension "d889" diameter = 3.3 (= "hw_m4_tappedwj")
  dimension "d890" distance = 5
  dimension "d891" distance = 10.275 (= "10 mm + preload_bearings / 2")
  dimension "d894" distance = 17.5
  dimension "d895" distance = 27.5
  dimension "d896" distance = 0.2
  dimension "d897" distance = 0.2 (= "d896")
  dimension "d900" distance = 6
  dimension "d902" distance = 3.7 (= "2 mm + 1.2 mm + 0.5 mm")
  dimension "d903" distance = 1
  dimension "d904" distance = 8
  dimension "d905" distance = 2.54
  dimension "d906" distance = 2.54
  dimension "d907" distance = 2.54
  dimension "d913" leftDistance = 1.5
  dimension "d915" distance = 5.65
  dimension "d916" distance = 14.65
  dimension "d917" distance = 14.65
  dimension "d920" ChordLen = 4
  dimension "d921" ChordLen = 1
  dimension "d923" distance = 2.54
  dimension "d924" Radius = 2
extrude "Extrude167" new body sketch "Sketch41" profile of L1 L2 L4 L6 L7 L9 C3 C4 L10 against normal blind 50
extrude "Extrude168" cut sketch "Sketch41" profile of L1 L2 L3 L4 C3 against normal blind 0.5
offset_faces "OffsetFaces11" distance -0.25
chamfer "Chamfer41" distance 0.5
sketch "Sketch42" plane through (0, 30, 0) normal (0, 1, 0) x axis (-1, 0, 0)
  line L1 (-8, 0) -> (22, 0)
  line L2 (-8, -50) -> (-8, 0)
  line L3 (22, -50) -> (-8, -50)
  line L4 (22, 0) -> (22, -50)
  line L5 (7, -5) -> (-3, -5)
  line L6 (7, -15) -> (7, -5)
  line L7 (-3, -15) -> (7, -15)
  line L8 (-3, -5) -> (-3, -15)
  circle C1 centre (-3, -5) radius 1.75
  circle C2 centre (7, -5) radius 1.75
  circle C3 centre (7, -15) radius 1.75
  circle C4 centre (-3, -15) radius 1.75
  circle C5 centre (-3, -5) radius 2.7
  circle C6 centre (7, -5) radius 2.7
  circle C7 centre (7, -15) radius 2.7
  circle C8 centre (-3, -15) radius 2.7
  circle C9 centre (17, -5) radius 1.75
  circle C10 centre (17, -5) radius 2.7
  point P6 (-3, -5)
  point P7 (-3, -5)
  point P8 (7, -5)
  point P11 (7, -5)
  point P9 (7, -15)
  point P12 (7, -15)
  point P10 (-3, -15)
  point P13 (-3, -15)
  point P15 (7, -5)
  point P18 (17, -5)
  point P19 (17, -5)
  horizontal L5
  vertical L6
  horizontal L7
  vertical L8
  coincident P6 P7
  equal L5 L8
  coincident P8 P11
  coincident P9 P12
  coincident P10 P13
  equal C1 C2
  equal C1 C3
  equal C1 C4
  concentric C1 C5
  concentric C2 C6
  concentric C3 C7
  concentric C4 C8
  equal C5 C6
  equal C5 C7
  equal C5 C8
  concentric C9 C10
  equal C1 C9
  equal C5 C10
  horizontal P15 P18
  dimension "d1585" distance L2 L8 = 5
  dimension "d1586" distance P7 P8 = 10
  dimension "d1587" distance L1 L5 = 5
  dimension "d1588" diameter C1 = 3.5
  dimension "d1589" diameter C5 = 5.4 (= "hw_m3insert_d")
  dimension "d1599" distance P15 P19 = 10
extrude "Extrude169" cut sketch "Sketch42" profile of C1 C3 C9 against normal blind 15
extrude "Extrude170" cut sketch "Sketch42" profile of C1 C3 C5 C7 C9 C10 against normal blind 5
chamfer "Chamfer42" distance 0.9
chamfer "Chamfer43" distance 0.5
rectangular_pattern "R-Pattern6" uSpaceDistance 20 vSpaceDistance 0
extrude "Extrude171" cut sketch "Sketch41" profile of L2 L4 C3 C4 L10 to an object from offset -22
chamfer "Chamfer44" distance 2.5
mirror "Mirror14"
combine "Combine23"
fillet "Fillet114" radius 0.5
sketch "Sketch43" plane through (0, 0, 0) normal (1, 0, 0) x axis (0, 1, 0)
  line L1 (-30, 63) -> (30, 63)
  line L2 (-30, 93) -> (-30, 63)
  line L3 (30, 93) -> (-30, 93)
  line L4 (30, 63) -> (30, 93)
  line L5 (30, -50) -> (30, 0)
  line L6 (-30, -50) -> (-30, 0)
  line L7 (-1.59, 122.985) -> (1.59, 122.985)
  line L8 (-4.765, 96) -> (-4.765, 114.5847)
  line L9 (4.765, 96) -> (-4.765, 96)
  line L10 (4.765, 114.5847) -> (4.765, 96)
  line L11 (-1.59, 132.515) -> (1.59, 132.515)
  line L12 (-4.765, 159.5) -> (-4.765, 140.9153)
  line L13 (4.765, 159.5) -> (-4.765, 159.5)
  line L14 (4.765, 140.9153) -> (4.765, 159.5)
  line L15 (6.75, 83) -> (6.75, 93)
  line L16 (4.25, 83) -> (6.75, 83)
  line L17 (4.25, 63) -> (4.25, 83)
  line L18 (1.59, 122.985) -> (1.59, 132.515)
  line L19 (-1.59, 122.985) -> (-1.59, 132.515)
  line L20 (-30, 93.1) -> (30, 93.1)
  line L21 (-30, 113.1) -> (-30, 93.1)
  line L22 (30, 113.1) -> (-30, 113.1)
  line L23 (30, 93.1) -> (30, 113.1)
  line L24 (0, 159.5) -> (0, 63)
  line L25 (13.215, 93.1) -> (13.215, 113.1)
  line L26 (13.115, 93.1) -> (13.115, 113.1)
  line L27 (-30, 212.5) -> (-30, 162.5)
  line L28 (30, 212.5) -> (-30, 212.5)
  line L29 (30, 162.5) -> (30, 212.5)
  line L30 (1.59, 127.75) -> (0, 127.75)
  line L31 (30, 162.5) -> (-30, 162.5)
  line L32 (-30, 162.4) -> (30, 162.4)
  arc A1 centre (14.29, 122.985) radius 12.7 clockwise from (4.765, 114.5847) to (1.59, 122.985)
  arc A2 centre (14.29, 132.515) radius 12.7 clockwise from (1.59, 132.515) to (4.765, 140.9153)
  arc A3 centre (-14.29, 132.515) radius 12.7 clockwise from (-4.765, 140.9153) to (-1.59, 132.515)
  arc A4 centre (-14.29, 122.985) radius 12.7 clockwise from (-1.59, 122.985) to (-4.765, 114.5847)
  circle C1 centre (9, 108.1) radius 1.575
  circle C2 centre (9, 98.1) radius 1.575
  circle C3 centre (9, 108.1) radius 2.7
  circle C4 centre (9, 98.1) radius 2.7
  point P2 (30, 63)
  point P6 (30, 63)
  point P15 (0, 96)
  point P1 (0, 0)
  point P16 (6.75, 93)
  point P19 (4.25, 63)
  point P30 (-4.765, 114.5847)
  point P24 (4.765, 114.5847)
  point P5 (30, 93)
  point P4 (-30, 93)
  point P38 (0, 63)
  point P39 (0, 159.5)
  point P36 (9, 108.1)
  point P41 (9, 98.1)
  point P42 (13.215, 113.1)
  point P43 (13.215, 93.1)
  point P44 (13.115, 113.1)
  point P45 (13.115, 93.1)
  point P46 (10.575, 108.1)
  point P47 (1.59, 127.75)
  point P48 (0, 127.75)
  point P53 (0, 127.75)
  point P54 (1.59, 127.75)
  point P7 (30, 0)
  point P9 (-30, 0)
  point P32 (30, 93.1)
  point P55 (30, 162.4)
  point P33 (-30, 93.1)
  point P56 (-30, 162.4)
  point P3 (-30, 63)
  point P12 (4.765, 96)
  point P18 (4.25, 83)
  point P35 (30, 113.1)
  point P37 (9, 98.1)
  point P40 (9, 108.1)
  point P50 (-30, 162.5)
  point P51 (-30, 212.5)
  horizontal L1
  perpendicular L1 L2
  perpendicular L2 L3
  perpendicular L3 L4
  coincident P2 P6
  horizontal L7
  vertical L8
  horizontal L9
  vertical L10
  horizontal L11
  vertical L12
  horizontal L13
  vertical L14
  midpoint L9 P15
  vertical P1 P15
  coincident L3 P16
  perpendicular L3 L15
  perpendicular L15 L16
  perpendicular L1 L17
  coincident L1 P19
  perpendicular L7 L18
  perpendicular L7 L19
  tangent L18 A1
  tangent L18 A2
  equal A1 A2
  tangent L19 A3
  tangent L19 A4
  equal A2 A4
  equal A2 A3
  coincident L12 P30
  coincident L14 P24
  horizontal L20
  vertical L21
  horizontal L22
  vertical L23
  coincident P5 L23
  coincident P4 L21
  midpoint L1 P38
  midpoint L13 P39
  equal L10 L14
  concentric C1 C3
  concentric C2 C4
  equal C3 C4
  equal C1 C2
  vertical P36 P41
  coincident L22 P42
  coincident L20 P43
  perpendicular L20 L25
  coincident L22 P44
  coincident L20 P45
  perpendicular L20 L26
  coincident C1 P46
  horizontal P36 P46
  midpoint L18 P47
  coincident L24 P48
  horizontal P47 P48
  vertical L27
  horizontal L28
  vertical L29
  coincident P48 P53
  coincident P47 P54
  coincident P7 L29
  coincident P9 L27
  perpendicular L27 L31
  symmetric P32 L30 P55
  symmetric P33 L30 P56
  dimension "d1598" distance P3 P4 = 30
  dimension "d1609" distance L1 P9 = 63
  dimension "d1610" distance P12 L13 = 63.5
  dimension "d1611" distance L7 L11 = 9.53
  dimension "d1612" distance P1 L17 = 4.25 (= "( 8.5 / 2 ) * 1 mm")
  dimension "d1613" distance P1 L15 = 6.75 (= "( 13.5 / 2 ) * 1 mm")
  dimension "d1614" distance P18 P19 = 20
  dimension "d1616" distance P15 L18 = 1.59 (= "( 3.18 / 2 ) * 1 mm")
  dimension "d1617" distance P15 L19 = 1.59 (= "d1616")
  dimension "d1618" radius A2 = 12.7
  dimension "d1619" distance L10 P15 = 4.765 (= "( 9.53 / 2 ) * 1 mm")
  dimension "d1620" distance L3 P15 = 3
  dimension "d1621" distance P32 P35 = 20
  dimension "d1622" distance L3 L20 = 0.1
  dimension "d1623" distance P1 L4 = 30
  dimension "d1624" distance P1 L2 = 30 (= "d1623")
  dimension "d1625" distance P36 P37 = 10
  dimension "d1626" distance L22 P36 = 5
  dimension "d1628" diameter C3 = 5.4 (= "hw_m3insert_d")
  dimension "d1629" diameter C1 = 3.15
  dimension "d1630" distance L24 P40 = 9
  dimension "d1665" distance L25 L26 = 0.1
  dimension "d1667" distance L26 P46 = 2.54
  dimension "d1688" distance P50 P51 = 50
  dimension "d1689" distance L20 P48 = 34.65
  dimension "d1690" distance L31 L32 = 0.1
extrude "Extrude172" sketch "Sketch43" profile of L1 L3 L4 L24 L27 L28 L29 L31 blind -20 bodies "Second"
extrude "Extrude173" cut sketch "Sketch41" profile of C3 L10 to an object
extrude "Extrude174" sketch "Sketch41" profile of L2 L4 C3 C4 L10 to an object from offset 20
sketch "Sketch44" plane through (0, 0, 93) normal (0, 0, 1) x axis (-1, 0, 0)
  line L1 (-8, 0) -> (-6.75, 0)
  line L2 (-8, -30) -> (-8, 0)
  line L3 (12, -30) -> (-8, -30)
  line L4 (12, 0) -> (12, -30)
  line L5 (6.75, 0) -> (12, 0)
  arc A1 centre (0, 0) radius 6.75 clockwise from (6.75, 0) to (-6.75, 0)
  circle C1 centre (-3, -25) radius 1.75
  circle C2 centre (7, -25) radius 1.75
  circle C3 centre (-3, -25) radius 2.7
  circle C4 centre (7, -25) radius 2.7
  circle C5 centre (-3, -17.5) radius 1.75
  circle C6 centre (-3, -17.5) radius 2.7
  circle C7 centre (7, -17.5) radius 1.75
  circle C8 centre (7, -17.5) radius 2.7
  point P9 (-3, -25)
  point P10 (7, -25)
  point P14 (-3, -17.5)
  point P13 (-3, -17.5)
  point P16 (7, -17.5)
  point P12 (7, -25)
  point P11 (-3, -25)
  horizontal P9 P10
  concentric C1 C3
  concentric C2 C4
  equal C3 C4
  equal C1 C2
  concentric C5 C6
  concentric C7 C8
  equal C1 C5
  equal C1 C7
  equal C3 C6
  equal C3 C8
  vertical P9 P14
  horizontal P13 P16
  vertical P12 P16
  dimension "d1642" distance L2 P9 = 5
  dimension "d1643" distance L4 P10 = 5
  dimension "d1644" distance L3 P9 = 5
  dimension "d1645" diameter C3 = 5.4 (= "hw_m3insert_d")
  dimension "d1646" diameter C1 = 3.5
  dimension "d1653" distance P11 P13 = 7.5
extrude "Extrude175" cut sketch "Sketch44" profile of C1 C2 C5 C7 against normal blind 20
extrude "Extrude176" cut sketch "Sketch44" profile of C1 C2 C3 C4 C5 C6 C7 C8 against normal blind 5
chamfer "Chamfer45" distance 0.9
chamfer "Chamfer46" distance 0.5
chamfer "Chamfer47" distance 2.5
chamfer "Chamfer48" distance 0.5
extrude "Extrude177" of existing geometry blind 0.5
extrude "Extrude178" new body sketch "Sketch43" profile of L9 L10 L20 L22 L23 L24 C3 C4 L25 L26 to an object bodies "Backing"
extrude "Extrude179" add sketch "Sketch43" profile of L20 L22 L23 L25 to an object
extrude "Extrude180" new body sketch "Sketch43" profile of L9 L10 L20 L22 C1 C2 L24 C3 C4 L26 to an object offset 4 bodies "Clamp"
extrude "Extrude181" cut sketch "Sketch43" profile of L9 L10 L22 L24 distance 0.5
offset_faces "OffsetFaces12" distance -0.25
extrude "Extrude189" add of existing geometry to an object offset -0.05
fillet "Fillet115" radius 0.5
chamfer "Chamfer49" distance 0.5
extrude "Extrude182" cut sketch "Sketch44" profile of C1 C2 C5 C7 to an object
chamfer "Chamfer50" distance 0.5
extrude "Extrude183" add sketch "Sketch43" profile of C1 C2 C3 C4 along normal blind 2
chamfer "Chamfer51" distance 1
chamfer "Chamfer52" distance 0.5
chamfer "Chamfer53" distance 0.5
fillet "Fillet116" radius 0.5
work_plane "WorkPlane2" AlongDistance 127.75
mirror "Mirror15" bodies "Backing (1)", "Clamp (1)"
extrude "Extrude184" add of existing geometry to an object
work_plane "WorkPlane3"
sketch "Sketch45" plane through (0, 30, 0) normal (0, 1, 0) x axis (-1, 0, 0)
  line L1 (-8, 162.5) -> (-8, 212.5)
  line L2 (22, 162.5) -> (-8, 162.5)
  line L3 (22, 212.5) -> (22, 162.5)
  line L4 (-8, 212.5) -> (22, 212.5)
  circle C1 centre (-3, 177.5) radius 1.575
  circle C2 centre (7, 177.5) radius 1.575
  circle C3 centre (17, 167.5) radius 1.575
  circle C4 centre (17, 167.5) radius 2.7
  circle C5 centre (7, 177.5) radius 2.7
  circle C6 centre (-3, 177.5) radius 2.7
  circle C7 centre (17, 187.5) radius 1.575
  circle C8 centre (17, 187.5) radius 2.7
  circle C9 centre (-3, 207.5) radius 1.575
  circle C10 centre (-3, 207.5) radius 2.7
  circle C11 centre (17, 207.5) radius 1.575
  circle C12 centre (17, 207.5) radius 2.7
  circle C13 centre (7, 197.5) radius 1.575
  circle C14 centre (7, 197.5) radius 2.7
  point P6 (-3, 177.5)
  point P10 (7, 177.5)
  point P11 (-3, 177.5)
  point P15 (-3, 207.5)
  point P8 (17, 167.5)
  point P17 (17, 207.5)
  point P16 (17, 207.5)
  point P13 (17, 187.5)
  point P7 (7, 177.5)
  point P19 (7, 197.5)
  point P14 (-3, 207.5)
  point P12 (17, 187.5)
  concentric C3 C4
  concentric C2 C5
  concentric C1 C6
  equal C5 C6
  equal C4 C6
  equal C2 C3
  equal C1 C2
  horizontal P6 P10
  concentric C7 C8
  concentric C9 C10
  concentric C11 C12
  concentric C13 C14
  equal C10 C12
  equal C10 C14
  equal C8 C10
  equal C6 C10
  equal C7 C13
  equal C9 C11
  equal C1 C9
  equal C9 C13
  vertical P11 P15
  vertical P8 P17
  horizontal P15 P16
  vertical P8 P13
  vertical P7 P19
  dimension "d1693" diameter C1 = 3.15
  dimension "d1694" diameter C6 = 5.4 (= "hw_m3insert_d")
  dimension "d1695" distance L1 P6 = 5
  dimension "d1697" distance L2 P11 = 15
  dimension "d1698" distance P7 P8 = 10
  dimension "d1699" distance P6 P10 = 10
  dimension "d1705" distance L2 P8 = 5
  dimension "d1708" distance P11 P15 = 30
  dimension "d1722" distance P14 P19 = 10
  dimension "d1723" distance P10 P12 = 10
extrude "Extrude185" cut sketch "Sketch45" profile of C1 C2 C3 C7 C9 C11 C13 against normal blind 20
extrude "Extrude186" cut sketch "Sketch45" profile of C1 C2 C3 C4 C5 C6 C7 C8 C9 C10 C11 C12 C13 C14 against normal blind 5
chamfer "Chamfer54" distance 1
chamfer "Chamfer55" distance 0.5
mirror "Mirror17"
extrude "Extrude187" sketch "Sketch44" profile of C1 C2 C5 C7 blind 10
extrude "Extrude188" sketch "Sketch44" profile of C1 C2 C3 C4 C5 C6 C7 C8 blind 5
chamfer "Chamfer56" distance 0.9
chamfer "Chamfer57" distance 0.5
mirror "Mirror18"
mirror "Mirror16" bodies "Backing (1) (1)", "Clamp (1) (1)", "Backing (2)", "Clamp (2)", "Second (1)"
combine "Combine24" bodies "Clamp (2)"
combine "Combine25" bodies "Clamp (1) (1)"
combine "Combine26" bodies "Backing (1) (1)"
combine "Combine27" bodies "Backing (2)"
combine "Combine28" bodies "Second (1)"
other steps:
step "Extrude70" AlongDistance -26 TaperAngle 0
step "Extrude71" ProfileOffset 0.5 AlongDistance 5 (= "t_bearings") TaperAngle 0
step "Extrude74" ProfileOffset 0 AlongDistance 3 TaperAngle 0
step "Extrude75" ProfileOffset 0 Side1Offset 0 TaperAngle 0
step "Extrude76" Side1Offset 0 TaperAngle 0
step "Extrude77" ProfileOffset 0 Side1Offset 0 TaperAngle 0
step "Extrude78" AlongDistance 12 TaperAngle 0
step "Extrude72" ProfileOffset 0 Side1Offset 0 TaperAngle 0
step "Extrude73" AlongDistance 32 TaperAngle 0
step "Extrude79" AlongDistance -37 TaperAngle 0
step "Extrude80" Side1Offset 0.5 TaperAngle 0
step "Extrude81" Side1Offset 0 TaperAngle 0
step "Extrude82" Side1Offset 0 TaperAngle 0
step "Mirror"
step "Extrude83" Side1Offset 0 TaperAngle 0
step "Extrude84" TaperAngle 0
step "Extrude85" Side1Offset 0 TaperAngle 0
step "Extrude86" Side1Offset 0 TaperAngle 0
step "Extrude93" Side1Offset 0 TaperAngle 0
step "Extrude94" ProfileOffset 0 Side1Offset 0 TaperAngle 0
step "Extrude95" Side1Offset 0 TaperAngle 0
step "Extrude87" AlongDistance -7 TaperAngle 0
step "Extrude88" ProfileOffset 0 Side1Offset 0 TaperAngle 0
step "Extrude89" ProfileOffset 0 Side1Offset 0 TaperAngle 0
step "Extrude90" Side1Offset 0 TaperAngle 0
step "Extrude92" TaperAngle 0
named bodies: "Second", "Backing", "Clamp", "Backing (1)", "Clamp (1)", "Backing (1) (1)", "Clamp (1) (1)", "Backing (2)", "Clamp (2)", "Second (1)"

design "rct-dex-squat"
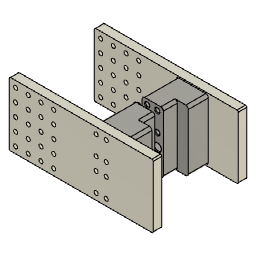
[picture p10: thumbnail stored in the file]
parameter "t_sheet_MAIN" = 6.7 comment "thickness of *most* of the gantry material"
parameter "t_sheet_SECOND" = 6.35 (= "1 / 4 * 1") comment "thickness of the webs"
parameter "od_bearings" = 16
parameter "id_bearings" = 5
parameter "t_bearings" = 5
parameter "p_belt" = 2
parameter "w_belt" = 10
parameter "t_belt" = 1.4
parameter "l_top_belt_to_rail" = 3
parameter "r_cutoutTool" = 2.05 (= "4.1 mm / 2")
parameter "hw_m3_thru" = 3.5
parameter "hw_m3_head" = 5.5
parameter "hw_m3_washer" = 7
parameter "hw_m3_thread" = 2.5
parameter "tab_breather" = 0.2 comment "tab clearance"
parameter "hw_m5_thread" = 4.2
parameter "hw_m5_head" = 8.5
parameter "hw_m5_washer" = 10
parameter "hw_m5_thru" = 5.25
parameter "hw_m6_thru" = 6.5
parameter "hw_m6_head" = 10
parameter "hw_m6_washer" = 12
parameter "l_beltblock" = 15
parameter "hw_plstf6_thread" = 2.94
parameter "hw_plstf6_thru" = 4
parameter "hw_plstf6_head" = 6.86
parameter "hw_plstf6_washer" = 7.92
parameter "hw_m3_flathead" = 6
parameter "hw_m4insert_d" = 6
parameter "hw_m4insert_l" = 4.8
parameter "hw_m4_tappedwj" = 3.3
parameter "hw_m4_thru" = 4.25
parameter "hw_m4_head" = 7
parameter "hw_m4_headheight" = 4
parameter "preload_bearings" = 0.55
parameter "hw_m3insert_d" = 5.4
parameter "hw_m3insert_l" = 3.8
parameter "dist_clearance" = 0.5
parameter "hw_shoulder_headDiameter" = 9
parameter "hw_shoulder_headHeight" = 4
parameter "l_travel" = 405 comment "will be rounded to 10s"
parameter "User Parameter" = 0 (= "min 10")
parameter "nh_rail_width" = "nh_gantry_width - 3"
parameter "l_shoulder_thread" = 10
parameter "hw_n6_thru" = 4.064
parameter "hw_n6_thread" = 3.1
parameter "hw_n6_flathead" = 6.6548
parameter "hw_n6_head" = 6.858
parameter "carriage_offsets" = 0.25
parameter "hw_momentPin_reald" = 3.683
parameter "pinch_by" = 0.2
parameter "d285" = 2
parameter "d344" = 3.5
parameter "d482" = 3.35 (= "t_sheet_MAIN / 2")
parameter "d578" = 0.5
parameter "d683" = 3.683 (= "hw_momentPin_reald")
parameter "d689" = 0.5
parameter "d698" = 5
parameter "d705" = 3.5415 (= "d683 / 2 + 1.7 mm")
parameter "d837" = 0.25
